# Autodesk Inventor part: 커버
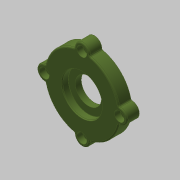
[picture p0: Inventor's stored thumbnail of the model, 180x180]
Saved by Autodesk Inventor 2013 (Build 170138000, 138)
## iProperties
Created: 2016-06
Part Number: 커버
Material: 알루미늄 6061
Document SubType Name: Modeling
Designer: mduedu
Density: 2.71 g/cm^3
Author: mduedu
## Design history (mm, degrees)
sketch "스케치1"
  geometry: C1 r 30 at (0, 0); 1 further point
  constraints: 1 centre point, 1 coincident
  dimensions: "d0" = 60 diameter of C1
extrude "돌출1" new body sketch "스케치1" distance "d2" = 10; taper "d3" = 0 deg
sketch "스케치5"
  geometry: C1 r 6 at (0, 30); 2 further points
  constraints: 2 vertical alignment, 1 centre point, 1 other
  dimensions: "d61" = 12 diameter of C1
extrude "돌출3" join sketch "스케치5" stored distance "d62" = 10; taper "d63" = 0 deg
sketch "스케치2"
  geometry: C1 r 21 at (0, 0); 1 further point
  constraints: 1 centre point, 1 coincident
  dimensions: "d4" = 42 diameter of C1
extrude "돌출2" join sketch "스케치2" distance "d6" = 3; taper "d7" = 0 deg
hole "구멍1" diameter "d11" = 35; stored, may be unused: countersink angle "d15" = 90 deg, drill point angle "d17" = 0 deg; dims "d9" = 10, "d10" = 10, "d12" = 6, "d13" = 4, "d14" = 2, "d16" = 3
hole "구멍2" diameter "d20" = 32; stored, may be unused: countersink angle "d24" = 90 deg, drill point angle "d26" = 0 deg; dims "d21" = 6, "d22" = 4, "d23" = 2, "d25" = 5.2, "d67" = 10, "d68" = 10
hole "구멍3" diameter "d29" = 21; stored, may be unused: countersink angle "d33" = 90 deg, drill point angle "d35" = 0 deg; dims "d27" = 10, "d28" = 10, "d30" = 6, "d31" = 4, "d32" = 2, "d34" = 5
fillet "모깎기2" dims "d36" = 3
fillet "모깎기3" dims "d37" = 0.1
chamfer "모따기1" distance "d38" = 0.75; stored, may be unused: second distance "d39" = 2, angle "d40" = 30 deg
chamfer "모따기2" distance "d42" = 0.5; stored, may be unused: second distance "d43" = 2, angle "d44" = 30 deg
sketch "스케치6"
  geometry: A1 r 30 centre (0, 0) between (29.4, 5.97) and (5.97, 29.4) reference; 3 further points
  constraints: 2 vertical alignment, 1 coincident, 3 other
hole "구멍5" sketch "스케치6" at (0, 30) diameter "d69" = 4.5; stored, may be unused: countersink angle "d73" = 90 deg, drill point angle "d75" = 118 deg; dims "d70" = 6, "d71" = 8, "d72" = 4.6, "d74" = 8
fillet "모깎기5" dims "d79" = 1
fillet "모깎기6" dims "d80" = 1
node "솔리드1"
pattern_circular "원형 패턴1" dims angle "d65" = 360 deg
pattern_circular "원형 패턴2" dims angle "d77" = 360 deg
node "투영된 루프1"
